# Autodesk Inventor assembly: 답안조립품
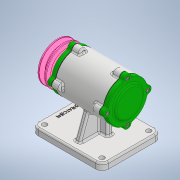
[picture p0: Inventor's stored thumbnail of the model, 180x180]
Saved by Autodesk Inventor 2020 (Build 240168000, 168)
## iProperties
Created: 2022-11
Part Number: 답안조립품
Document SubType Name: Assembly
Designer: owner
Author: owner
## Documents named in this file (12)
- C:\Users\owner\Desktop\721108V1014\답안조립품.iam
- C:\Users\owner\Desktop\721108V1014\본체.ipt
- C:\Users\owner\Desktop\721108V1014\볼트 M4 x 12.ipt
- C:\Users\owner\Desktop\721108V1014\앞커버.ipt
- C:\Users\owner\Desktop\721108V1014\오일 실.ipt
- C:\Users\owner\Desktop\721108V1014\축.ipt
- C:\Users\owner\Desktop\721108V1014\키 4 x 4.ipt
- C:\Users\owner\Desktop\721108V1014\V-벨트풀리.ipt
- C:\Users\owner\Desktop\721108V1014\개스킷.ipt
- C:\Users\owner\Desktop\721108V1014\너트 M12 x 1.25.ipt
- C:\Users\owner\Desktop\721108V1014\뒤커버.ipt
- C:\Users\owner\Desktop\721108V1014\베어링 6204.ipt
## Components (8 placed, 6 different names)
1. KS B 2804 D D - 20 32 8:1
2. KS B 1311 (I) 4 x 4 x 12:1
3. V-벨트풀리:1
4. 개스킷:1
5. KS B 1012 클래스 1 일반 - 미터 M12x1.25:1
6. KS B 2023 6204 - 20 x 47 x 14:1
7. KS B 2023 6204 - 20 x 47 x 14:2
8. 개스킷:2
